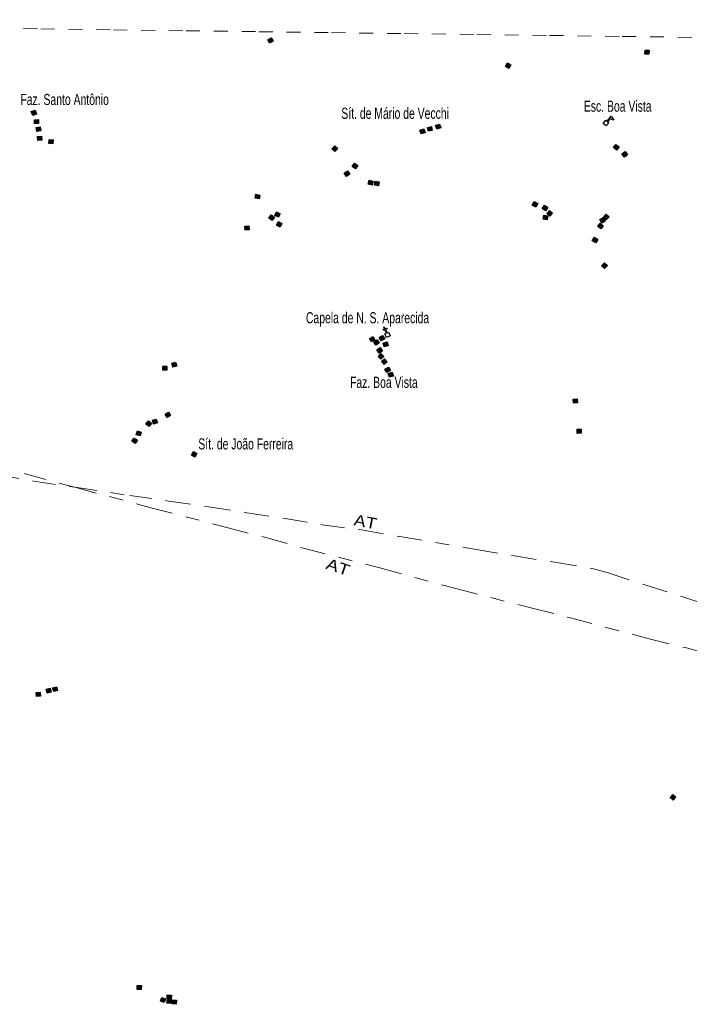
# Model space of a CAD drawing. Extents: x 679 to 705, y 7427.4 to 7455.4.
# Drawn here: x 692.82 to 697.64, y 7448.18 to 7455.27 of the extents above; entities that cross this region are included whole.
import ezdxf
from ezdxf.enums import TextEntityAlignment as Align

# ---------------------------------------------------------------- set-up
doc = ezdxf.new("R2010")
doc.units = 0
doc.header["$LTSCALE"] = 0.032
doc.linetypes.add('DOT_DASHED', pattern=[7.7, 5, -1.2, 0.3, -1.2])
doc.linetypes.add('SHORT_DASHED', pattern=[2.7, 1.5, -1.2])
for name, color, linetype, lineweight in [('2', 7, 'Continuous', 25), ('4', 7, 'Continuous', 25), ('56', 7, 'DOT_DASHED', 13), ('58', 7, 'SHORT_DASHED', 13), ('6', 7, 'Continuous', 25)]:
    doc.layers.add(name, color=color, linetype=linetype, lineweight=lineweight)
doc.layers.add('61', color=7, linetype='Continuous')

msp = doc.modelspace()

# ---------------------------------------------------------------- hatches: boundary and pattern name
at = {"layer": '2'}
for points in [[(694.6281, 7455.1437), (694.6422, 7455.1184), (694.6168, 7455.1043), (694.6028, 7455.1296)], [(697.3473, 7455.054), (697.3457, 7455.025), (697.3168, 7455.0266), (697.3184, 7455.0556)], [(696.3278, 7454.9624), (696.353, 7454.9481), (696.3386, 7454.9229), (696.3134, 7454.9372)], [(692.9293, 7454.6217), (692.9389, 7454.5944), (692.9116, 7454.5847), (692.9019, 7454.6121)], [(692.9526, 7454.5548), (692.9538, 7454.5258), (692.9248, 7454.5246), (692.9236, 7454.5536)], [(692.9654, 7454.5025), (692.9696, 7454.4738), (692.9409, 7454.4696), (692.9367, 7454.4983)], [(695.7253, 7454.4878), (695.7347, 7454.4604), (695.7072, 7454.451), (695.6979, 7454.4785)], [(695.7805, 7454.5055), (695.7871, 7454.4772), (695.7589, 7454.4706), (695.7523, 7454.4988)], [(695.8387, 7454.5227), (695.8477, 7454.4951), (695.8201, 7454.4862), (695.8112, 7454.5137)], [(692.9766, 7454.4058), (692.9476, 7454.4049), (692.9467, 7454.4339), (692.9757, 7454.4348)], [(693.0587, 7454.4095), (693.0574, 7454.3805), (693.0284, 7454.3818), (693.0297, 7454.4108)], [(695.085, 7454.3661), (695.1062, 7454.3464), (695.0865, 7454.3252), (695.0652, 7454.3449)], [(697.1079, 7454.3762), (697.1311, 7454.3588), (697.1136, 7454.3356), (697.0905, 7454.353)], [(697.1749, 7454.3251), (697.1925, 7454.302), (697.1694, 7454.2845), (697.1518, 7454.3076)], [(695.2285, 7454.2408), (695.2515, 7454.2232), (695.2339, 7454.2002), (695.2109, 7454.2178)], [(695.1775, 7454.1851), (695.1933, 7454.1607), (695.169, 7454.1449), (695.1532, 7454.1693)], [(695.361, 7454.1103), (695.3538, 7454.0822), (695.3257, 7454.0894), (695.3329, 7454.1175)], [(695.4053, 7454.1056), (695.4008, 7454.077), (695.3721, 7454.0815), (695.3766, 7454.1101)], [(694.5185, 7454.0176), (694.5468, 7454.0112), (694.5404, 7453.9829), (694.5121, 7453.9893)], [(696.5203, 7453.9641), (696.546, 7453.9508), (696.5327, 7453.9251), (696.5069, 7453.9384)], [(694.6666, 7453.8899), (694.6926, 7453.8771), (694.6798, 7453.8511), (694.6538, 7453.8639)], [(696.5945, 7453.938), (696.6185, 7453.9217), (696.6022, 7453.8977), (696.5782, 7453.914)], [(696.6302, 7453.8992), (696.6516, 7453.8796), (696.6319, 7453.8583), (696.6106, 7453.8779)], [(694.6288, 7453.8681), (694.6521, 7453.8509), (694.6349, 7453.8276), (694.6115, 7453.8448)], [(694.6795, 7453.8201), (694.7051, 7453.8064), (694.6914, 7453.7809), (694.6658, 7453.7946)], [(696.6182, 7453.8604), (696.6132, 7453.8318), (696.5846, 7453.8368), (696.5897, 7453.8654)], [(697.0167, 7453.8493), (697.0312, 7453.8241), (697.0061, 7453.8097), (696.9916, 7453.8348)], [(697.0389, 7453.8746), (697.0589, 7453.8536), (697.0379, 7453.8336), (697.0179, 7453.8545)], [(694.4385, 7453.7878), (694.4675, 7453.789), (694.4686, 7453.76), (694.4396, 7453.7589)], [(696.9954, 7453.8086), (697.0178, 7453.7901), (696.9993, 7453.7677), (696.9769, 7453.7862)], [(696.9534, 7453.7071), (696.9783, 7453.6923), (696.9635, 7453.6674), (696.9386, 7453.6822)], [(697.0252, 7453.5225), (697.0466, 7453.5029), (697.027, 7453.4815), (697.0056, 7453.5011)], [(695.3618, 7452.9918), (695.3744, 7452.9657), (695.3482, 7452.9532), (695.3357, 7452.9793)], [(695.3915, 7452.9695), (695.4057, 7452.9442), (695.3804, 7452.9301), (695.3662, 7452.9554)], [(695.4299, 7453.0006), (695.445, 7452.9759), (695.4203, 7452.9607), (695.4052, 7452.9854)], [(695.4131, 7452.9122), (695.4287, 7452.8877), (695.4043, 7452.8721), (695.3886, 7452.8965)], [(695.4616, 7452.9534), (695.4695, 7452.9255), (695.4415, 7452.9177), (695.4337, 7452.9456)], [(695.4177, 7452.8693), (695.4376, 7452.8482), (695.4165, 7452.8283), (695.3966, 7452.8494)], [(695.4428, 7452.8323), (695.4622, 7452.8107), (695.4407, 7452.7913), (695.4213, 7452.8128)], [(693.8766, 7452.7794), (693.8766, 7452.7504), (693.8476, 7452.7504), (693.8476, 7452.7794)], [(693.9403, 7452.8072), (693.948, 7452.7793), (693.92, 7452.7716), (693.9124, 7452.7995)], [(695.4714, 7452.772), (695.4861, 7452.7469), (695.461, 7452.7323), (695.4464, 7452.7574)], [(695.498, 7452.7356), (695.5069, 7452.708), (695.4793, 7452.699), (695.4704, 7452.7266)], [(696.83, 7452.5435), (696.8319, 7452.5146), (696.8029, 7452.5127), (696.801, 7452.5417)], [(693.8006, 7452.3977), (693.8092, 7452.37), (693.7814, 7452.3615), (693.7729, 7452.3892)], [(693.8887, 7452.4488), (693.9038, 7452.424), (693.879, 7452.4089), (693.8639, 7452.4337)], [(693.7439, 7452.3853), (693.7668, 7452.3674), (693.7489, 7452.3446), (693.7261, 7452.3624)], [(693.6421, 7452.2616), (693.6659, 7452.245), (693.6493, 7452.2212), (693.6255, 7452.2378)], [(693.665, 7452.3129), (693.6928, 7452.3048), (693.6847, 7452.2769), (693.6568, 7452.2851)], [(696.8588, 7452.3246), (696.8593, 7452.2957), (696.8303, 7452.2951), (696.8298, 7452.3241)], [(694.0683, 7452.1644), (694.0935, 7452.1501), (694.0791, 7452.1248), (694.0539, 7452.1392)], [(692.9649, 7450.4304), (692.9674, 7450.4015), (692.9385, 7450.3989), (692.936, 7450.4278)], [(693.0378, 7450.4589), (693.044, 7450.4306), (693.0157, 7450.4244), (693.0095, 7450.4527)], [(693.0832, 7450.4706), (693.0909, 7450.4427), (693.0629, 7450.435), (693.0552, 7450.4629)], [(697.5174, 7449.6955), (697.5391, 7449.6763), (697.5199, 7449.6546), (697.4982, 7449.6738)], [(693.6936, 7448.3189), (693.6929, 7448.2899), (693.6639, 7448.2906), (693.6646, 7448.3196)], [(693.8679, 7448.2225), (693.8576, 7448.1954), (693.8305, 7448.2058), (693.8409, 7448.2329)], [(693.9101, 7448.217), (693.9066, 7448.1882), (693.8778, 7448.1917), (693.8813, 7448.2205)], [(693.9094, 7448.2496), (693.9075, 7448.2207), (693.8785, 7448.2227), (693.8805, 7448.2516)], [(693.9468, 7448.2122), (693.9433, 7448.1834), (693.9145, 7448.1869), (693.918, 7448.2157)]]:
    msp.add_hatch(color=256, dxfattribs=at).paths.add_polyline_path(points)

# ---------------------------------------------------------------- linework, layer by layer
for points in [[(694.6281, 7455.1437), (694.6422, 7455.1184), (694.6168, 7455.1043), (694.6028, 7455.1296)], [(697.3473, 7455.054), (697.3457, 7455.025), (697.3168, 7455.0266), (697.3184, 7455.0556)], [(696.3278, 7454.9624), (696.353, 7454.9481), (696.3386, 7454.9229), (696.3134, 7454.9372)], [(692.9293, 7454.6217), (692.9389, 7454.5944), (692.9116, 7454.5847), (692.9019, 7454.6121)], [(692.9526, 7454.5548), (692.9538, 7454.5258), (692.9248, 7454.5246), (692.9236, 7454.5536)], [(692.9654, 7454.5025), (692.9696, 7454.4738), (692.9409, 7454.4696), (692.9367, 7454.4983)], [(695.7253, 7454.4878), (695.7347, 7454.4604), (695.7072, 7454.451), (695.6979, 7454.4785)], [(695.7805, 7454.5055), (695.7871, 7454.4772), (695.7589, 7454.4706), (695.7523, 7454.4988)], [(695.8387, 7454.5227), (695.8477, 7454.4951), (695.8201, 7454.4862), (695.8112, 7454.5137)], [(692.9766, 7454.4058), (692.9476, 7454.4049), (692.9467, 7454.4339), (692.9757, 7454.4348)], [(693.0587, 7454.4095), (693.0574, 7454.3805), (693.0284, 7454.3818), (693.0297, 7454.4108)], [(695.085, 7454.3661), (695.1062, 7454.3464), (695.0865, 7454.3252), (695.0652, 7454.3449)], [(697.1079, 7454.3762), (697.1311, 7454.3588), (697.1136, 7454.3356), (697.0905, 7454.353)], [(697.1749, 7454.3251), (697.1925, 7454.302), (697.1694, 7454.2845), (697.1518, 7454.3076)], [(695.2285, 7454.2408), (695.2515, 7454.2232), (695.2339, 7454.2002), (695.2109, 7454.2178)], [(695.1775, 7454.1851), (695.1933, 7454.1607), (695.169, 7454.1449), (695.1532, 7454.1693)], [(695.361, 7454.1103), (695.3538, 7454.0822), (695.3257, 7454.0894), (695.3329, 7454.1175)], [(695.4053, 7454.1056), (695.4008, 7454.077), (695.3721, 7454.0815), (695.3766, 7454.1101)], [(694.5185, 7454.0176), (694.5468, 7454.0112), (694.5404, 7453.9829), (694.5121, 7453.9893)], [(696.5203, 7453.9641), (696.546, 7453.9508), (696.5327, 7453.9251), (696.5069, 7453.9384)], [(694.6666, 7453.8899), (694.6926, 7453.8771), (694.6798, 7453.8511), (694.6538, 7453.8639)], [(696.5945, 7453.938), (696.6185, 7453.9217), (696.6022, 7453.8977), (696.5782, 7453.914)], [(696.6302, 7453.8992), (696.6516, 7453.8796), (696.6319, 7453.8583), (696.6106, 7453.8779)], [(694.6288, 7453.8681), (694.6521, 7453.8509), (694.6349, 7453.8276), (694.6115, 7453.8448)], [(694.6795, 7453.8201), (694.7051, 7453.8064), (694.6914, 7453.7809), (694.6658, 7453.7946)], [(696.6182, 7453.8604), (696.6132, 7453.8318), (696.5846, 7453.8368), (696.5897, 7453.8654)], [(697.0167, 7453.8493), (697.0312, 7453.8241), (697.0061, 7453.8097), (696.9916, 7453.8348)], [(697.0389, 7453.8746), (697.0589, 7453.8536), (697.0379, 7453.8336), (697.0179, 7453.8545)], [(694.4385, 7453.7878), (694.4675, 7453.789), (694.4686, 7453.76), (694.4396, 7453.7589)], [(696.9954, 7453.8086), (697.0178, 7453.7901), (696.9993, 7453.7677), (696.9769, 7453.7862)], [(696.9534, 7453.7071), (696.9783, 7453.6923), (696.9635, 7453.6674), (696.9386, 7453.6822)], [(697.0252, 7453.5225), (697.0466, 7453.5029), (697.027, 7453.4815), (697.0056, 7453.5011)], [(695.3618, 7452.9918), (695.3744, 7452.9657), (695.3482, 7452.9532), (695.3357, 7452.9793)], [(695.3915, 7452.9695), (695.4057, 7452.9442), (695.3804, 7452.9301), (695.3662, 7452.9554)], [(695.4299, 7453.0006), (695.445, 7452.9759), (695.4203, 7452.9607), (695.4052, 7452.9854)], [(695.4131, 7452.9122), (695.4287, 7452.8877), (695.4043, 7452.8721), (695.3886, 7452.8965)], [(695.4616, 7452.9534), (695.4695, 7452.9255), (695.4415, 7452.9177), (695.4337, 7452.9456)], [(695.4177, 7452.8693), (695.4376, 7452.8482), (695.4165, 7452.8283), (695.3966, 7452.8494)], [(695.4428, 7452.8323), (695.4622, 7452.8107), (695.4407, 7452.7913), (695.4213, 7452.8128)], [(693.8766, 7452.7794), (693.8766, 7452.7504), (693.8476, 7452.7504), (693.8476, 7452.7794)], [(693.9403, 7452.8072), (693.948, 7452.7793), (693.92, 7452.7716), (693.9124, 7452.7995)], [(695.4714, 7452.772), (695.4861, 7452.7469), (695.461, 7452.7323), (695.4464, 7452.7574)], [(695.498, 7452.7356), (695.5069, 7452.708), (695.4793, 7452.699), (695.4704, 7452.7266)], [(696.83, 7452.5435), (696.8319, 7452.5146), (696.8029, 7452.5127), (696.801, 7452.5417)], [(693.8006, 7452.3977), (693.8092, 7452.37), (693.7814, 7452.3615), (693.7729, 7452.3892)], [(693.8887, 7452.4488), (693.9038, 7452.424), (693.879, 7452.4089), (693.8639, 7452.4337)], [(693.7439, 7452.3853), (693.7668, 7452.3674), (693.7489, 7452.3446), (693.7261, 7452.3624)], [(693.6421, 7452.2616), (693.6659, 7452.245), (693.6493, 7452.2212), (693.6255, 7452.2378)], [(693.665, 7452.3129), (693.6928, 7452.3048), (693.6847, 7452.2769), (693.6568, 7452.2851)], [(696.8588, 7452.3246), (696.8593, 7452.2957), (696.8303, 7452.2951), (696.8298, 7452.3241)], [(694.0683, 7452.1644), (694.0935, 7452.1501), (694.0791, 7452.1248), (694.0539, 7452.1392)], [(692.9649, 7450.4304), (692.9674, 7450.4015), (692.9385, 7450.3989), (692.936, 7450.4278)], [(693.0378, 7450.4589), (693.044, 7450.4306), (693.0157, 7450.4244), (693.0095, 7450.4527)], [(693.0832, 7450.4706), (693.0909, 7450.4427), (693.0629, 7450.435), (693.0552, 7450.4629)], [(697.5174, 7449.6955), (697.5391, 7449.6763), (697.5199, 7449.6546), (697.4982, 7449.6738)], [(693.6936, 7448.3189), (693.6929, 7448.2899), (693.6639, 7448.2906), (693.6646, 7448.3196)], [(693.8679, 7448.2225), (693.8576, 7448.1954), (693.8305, 7448.2058), (693.8409, 7448.2329)], [(693.9101, 7448.217), (693.9066, 7448.1882), (693.8778, 7448.1917), (693.8813, 7448.2205)], [(693.9094, 7448.2496), (693.9075, 7448.2207), (693.8785, 7448.2227), (693.8805, 7448.2516)], [(693.9468, 7448.2122), (693.9433, 7448.1834), (693.9145, 7448.1869), (693.918, 7448.2157)]]:
    msp.add_lwpolyline(points, close=True, dxfattribs=at)
at = {"layer": '4'}
for points in [[(697.0481, 7454.5394), (697.0574, 7454.5317), (697.039, 7454.5093), (697.0166, 7454.5277), (697.035, 7454.5501), (697.0443, 7454.5425)], [(697.0443, 7454.5425), (697.075, 7454.5799), (697.0938, 7454.5494), (697.0646, 7454.5596), (697.0481, 7454.5394)]]:
    msp.add_lwpolyline(points, dxfattribs=at)
at = {"layer": '56'}
for points in [[(685.0003, 7453.9163), (685.013, 7453.9116), (685.2285, 7453.8725), (685.5082, 7453.8208), (686.0678, 7453.7211), (686.3459, 7453.6633), (686.9027, 7453.5508), (687.4611, 7453.431), (688.0181, 7453.2912), (688.5601, 7453.1499), (689.1094, 7453.0028), (689.6616, 7452.8679), (690.2157, 7452.7249), (690.7571, 7452.5778), (691.3047, 7452.426), (691.5859, 7452.3484), (692.4067, 7452.1254), (693.1904, 7451.9134), (693.214, 7451.907)], [(688.5663, 7451.5305), (688.7265, 7451.6388), (688.9692, 7451.7931), (689.2108, 7451.9345), (689.4472, 7452.0863), (689.6965, 7452.2391), (690.0165, 7452.2624), (690.3273, 7452.2423), (690.6141, 7452.2221), (690.8921, 7452.2041), (691.1848, 7452.1818), (691.4685, 7452.1552), (691.7475, 7452.1319), (692.0371, 7452.1022), (692.3622, 7452.0468), (692.6549, 7451.9969), (692.9176, 7451.9512), (693.1955, 7451.9095), (693.214, 7451.907)], [(693.214, 7451.909), (693.214, 7451.907), (693.7615, 7451.7595), (694.3078, 7451.6172), (694.5889, 7451.5442), (694.861, 7451.4682), (695.4101, 7451.3257), (695.9567, 7451.1767), (696.5056, 7451.0361), (696.7807, 7450.9661), (697.3373, 7450.8186), (697.6154, 7450.7502), (698.1624, 7450.6006)], [(693.214, 7451.907), (693.6098, 7451.8472), (693.8898, 7451.8079), (694.1759, 7451.7651), (694.4538, 7451.7237), (694.7281, 7451.6813), (694.9965, 7451.6356), (695.2782, 7451.6006), (695.5529, 7451.5518), (696.1018, 7451.4591), (696.3776, 7451.4124), (696.6678, 7451.3667), (696.9468, 7451.32), (697.0518, 7451.2914), (697.3241, 7451.2011), (697.5893, 7451.1173), (697.8488, 7451.0324)]]:
    msp.add_lwpolyline(points, dxfattribs=at)
at = {"layer": '58'}
msp.add_lwpolyline([(687.7386, 7455.2741), (688.2617, 7455.2676), (688.7848, 7455.261), (689.3078, 7455.2544), (689.8309, 7455.2478), (690.354, 7455.2412), (690.8771, 7455.2346), (691.4002, 7455.2279), (691.9232, 7455.2213), (692.4463, 7455.2146), (692.9694, 7455.2079), (693.4925, 7455.2011), (694.0156, 7455.1944), (694.5387, 7455.1876), (695.0618, 7455.1808), (695.5848, 7455.174), (696.1079, 7455.1672), (696.631, 7455.1604), (697.1541, 7455.1535), (697.6772, 7455.1467)], dxfattribs=at)
at = {"layer": '6'}
for points in [[(695.4568, 7453.0167), (695.4459, 7453.0415), (695.4348, 7453.0366), (695.4328, 7453.0411), (695.4439, 7453.046), (695.4373, 7453.061), (695.4417, 7453.0629), (695.4483, 7453.0479), (695.4594, 7453.0528), (695.4614, 7453.0483), (695.4503, 7453.0434), (695.4612, 7453.0186)], [(695.4612, 7453.0186), (695.4723, 7453.0235), (695.4839, 7452.997), (695.4574, 7452.9853), (695.4457, 7453.0118), (695.4568, 7453.0167)]]:
    msp.add_lwpolyline(points, dxfattribs=at)

# ---------------------------------------------------------------- texts
at = {"layer": '61', "width": 0.7}
for s, p in [('Faz. Santo Antônio', (692.8231, 7454.6597)), ('Esc. Boa Vista', (696.8777, 7454.6113)), ('Sít. de Mário de Vecchi', (695.1326, 7454.5601)), ('Capela de N. S. Aparecida', (694.8779, 7453.0878)), ('Faz. Boa Vista', (695.1951, 7452.6229)), ('Sít. de João Ferreira', (694.1035, 7452.1792))]:
    msp.add_text(s, height=0.08, dxfattribs=at).set_placement(p)
at = {"layer": '61'}
for rotation, width, p in [(349.028, 1.2, (695.2981, 7451.6187)), (340.938, 1.25, (695.096, 7451.2946))]:
    msp.add_text('AT', height=0.08, rotation=rotation, dxfattribs=dict(at, width=width)).set_placement(p, align=Align.CENTER)

doc.saveas('drawing.dxf')
